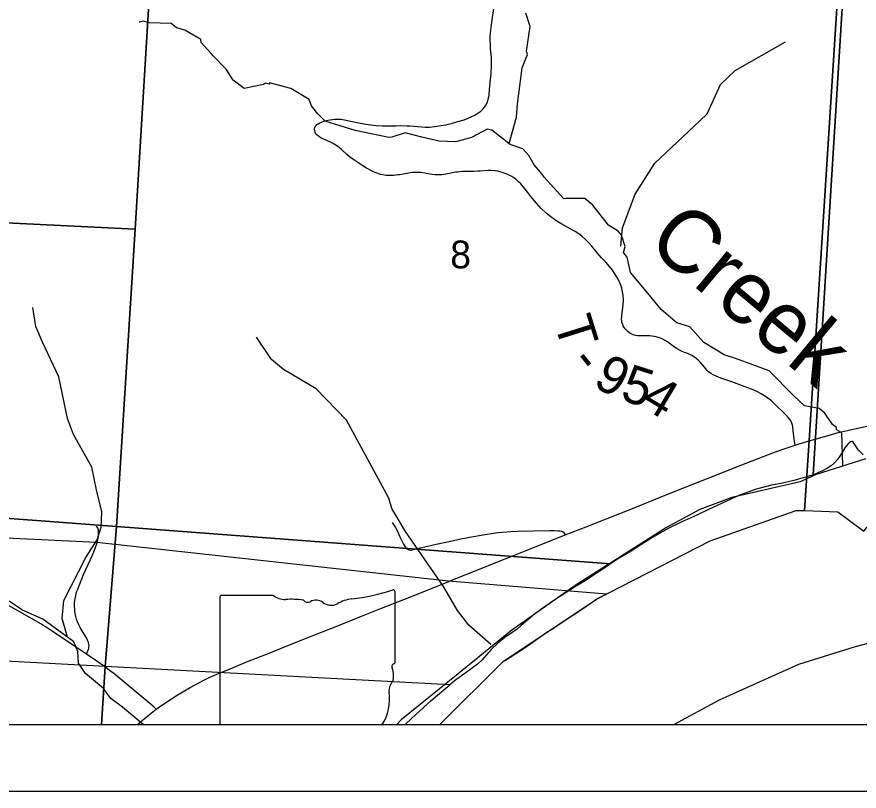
# Model space of a CAD drawing. Extents: x -2.1 to 31.9, y 6.3 to 28.3.
# Drawn here: x 3.117 to 4.384, y 20.344 to 21.508 of the extents above; entities that cross this region are included whole.
import ezdxf

# ---------------------------------------------------------------- set-up
doc = ezdxf.new("R2010")
doc.units = 0
for name, color, linetype in [('Default', 7, 'Continuous'), ('GM_X_Major_River', 7, 'Continuous'), ('GM_X_Minor_River', 7, 'Continuous'), ('GM_X_Minor_River_Text', 7, 'Continuous'), ('GM_X_Section', 7, 'Continuous'), ('GM_X_Section_Text', 7, 'Continuous'), ('GM_X_State_Location', 7, 'Continuous'), ('GM_X_State_Route', 7, 'Continuous'), ('GM_X_Township_Road', 7, 'Continuous'), ('GM_X_Township_Road_Text', 7, 'Continuous'), ('SH_Cut_Line', 7, 'Continuous'), ('SH_Data', 7, 'Continuous')]:
    doc.layers.add(name, color=color, linetype=linetype)

msp = doc.modelspace()

# ---------------------------------------------------------------- linework, layer by layer
at = {"layer": 'Default'}
msp.add_line((3.5023, 20.6384), (3.425, 20.6384), dxfattribs=at)
for points in [[(0.0344, 26.1105), (0.0344, 20.444), (3.7533, 20.444), (3.8489, 20.5389), (3.9894, 20.6326), (4.16, 20.7203), (4.2895, 20.7662), (4.3023, 20.7658), (4.3091, 20.8714), (4.3751, 21.8979), (4.4168, 22.5238), (4.4383, 22.8067), (4.4651, 23.2405), (4.4901, 23.6442), (4.5473, 24.5954), (4.5667, 24.9084), (4.6032, 25.4816), (4.6286, 25.8765), (3.8625, 25.9158), (3.0763, 25.9555), (2.8034, 25.9683), (2.0757, 26.0047), (0.4641, 26.0883)], [(2.565, 20.444), (3.7533, 20.444), (3.8489, 20.5389), (3.8524, 20.5411), (3.8819, 20.56), (3.9131, 20.5819), (3.9243, 20.5893), (3.9388, 20.5991), (3.9535, 20.6088), (3.9664, 20.6173), (3.9829, 20.6284), (3.9898, 20.633), (3.9977, 20.637), (4.0042, 20.6402), (3.7666, 20.6598), (3.2373, 20.718), (2.9743, 20.7306), (2.8967, 20.6256), (2.8379, 20.7139), (2.7774, 20.717)], [(2.8922, 20.444), (3.2442, 20.444), (3.25, 20.5316), (2.4442, 20.5745), (2.2124, 20.5868), (2.2056, 20.479)], [(3.2442, 20.444), (3.7013, 20.444), (3.711, 20.4531), (3.7405, 20.4805), (3.7595, 20.4964), (3.7685, 20.504), (3.25, 20.5316)]]:
    msp.add_lwpolyline(points, close=True, dxfattribs=at)
for points in [[(4.4901, 23.6442), (4.4651, 23.2405), (4.4383, 22.8067), (4.4168, 22.5238), (4.3751, 21.8979), (4.3091, 20.8714), (4.3023, 20.7658), (4.3525, 20.764), (4.3916, 20.7347), (4.4406, 20.7955), (4.5025, 20.8232), (4.6795, 20.8531), (4.9328, 20.8577), (5.1211, 20.8684), (5.1462, 20.8673), (5.351, 20.8306)], [(3.6862, 20.5387), (3.6861, 20.5387), (3.6862, 20.5387), (3.6862, 20.6436)], [(3.4225, 20.635), (3.4225, 20.444), (3.6669, 20.444)]]:
    msp.add_lwpolyline(points, dxfattribs=at)
for centre, radius, start, end in [((3.4255, 20.6354), 0.00305, 98.978, 188.5967), ((3.5207, 20.6617), 0.0296, 231.6404, 271.1117), ((3.5922, 20.9113), 0.2796, 275.8445, 288.9065), ((3.6832, 20.6438), 0.00294, 355.0978, 97.738), ((3.5305, 20.5261), 0.1064, 80.4867, 94.9883), ((3.5547, 20.6365), 0.00855, 219.7921, 297.1024), ((3.5672, 20.6133), 0.0178, 54.4667, 119.1411), ((3.5902, 20.645), 0.0214, 233.8562, 294.8282), ((3.6279, 20.5773), 0.0563, 97.3462, 120.7689), ((3.6855, 20.531), 0.00454, 107.944, 210.337), ((3.683, 20.5383), 0.00314, 289.6038, 7.7341), ((3.6566, 20.5178), 0.0273, 340.033, 23.6496), ((3.6967, 20.4949), 0.0198, 136.8065, 186.9296), ((3.6079, 20.4816), 0.0699, 327.459, 8.9858)]:
    msp.add_arc(centre, radius, start, end, dxfattribs=at)
at = {"layer": 'GM_X_Major_River'}
msp.add_line((4.3946, 20.8439), (4.3197, 20.8204), dxfattribs=at)
for points in [[(4.3197, 20.8204), (4.2959, 20.8093), (4.193, 20.7857), (4.1446, 20.7674), (4.0944, 20.7405), (3.9572, 20.6531), (3.8597, 20.5843), (3.7811, 20.5205), (3.6953, 20.451), (3.6885, 20.444)], [(4.1054, 20.444), (4.1745, 20.4812), (4.1896, 20.4881), (4.2939, 20.5348), (4.379, 20.5615), (4.4841, 20.5889), (4.5359, 20.5965), (4.5718, 20.5943), (4.6974, 20.5759), (4.7587, 20.579), (4.8729, 20.5765), (4.8861, 20.5738), (4.9474, 20.544), (4.9694, 20.5322), (5.0042, 20.519), (5.0757, 20.5039), (5.1135, 20.5021)]]:
    msp.add_lwpolyline(points, dxfattribs=at)
at = {"layer": 'GM_X_Minor_River'}
for points in [[(3.8577, 21.318), (3.8686, 21.3573), (3.8704, 21.377), (3.8772, 21.4318), (3.8855, 21.4516), (3.884, 21.4569), (3.8896, 21.4941), (3.8828, 21.5139)], [(3.8249, 21.3393), (3.8009, 21.3271), (3.7775, 21.3202), (3.7526, 21.3213), (3.7261, 21.3277), (3.7011, 21.3341), (3.6811, 21.3276), (3.6769, 21.3268), (3.6259, 21.3377), (3.5809, 21.3517), (3.5696, 21.3627), (3.5601, 21.3748), (3.5567, 21.3843), (3.5291, 21.4006), (3.4973, 21.4092), (3.4969, 21.407), (3.4913, 21.4088), (3.4882, 21.4069), (3.4588, 21.4004), (3.4425, 21.4133), (3.4319, 21.4296), (3.413, 21.4493), (3.4092, 21.4531), (3.3944, 21.4698), (3.3937, 21.4744), (3.3698, 21.4884), (3.357, 21.4918), (3.349, 21.4982), (3.3162, 21.4993), (3.3075, 21.5019), (3.3014, 21.5004), (3.301, 21.5004)], [(4.026, 21.1635), (4.0282, 21.1912), (4.0475, 21.2418), (4.0769, 21.2882), (4.1447, 21.3518), (4.1557, 21.3628), (4.1757, 21.4069), (4.198, 21.4279), (4.2737, 21.471)], [(3.8874, 21.3001), (3.8781, 21.3098), (3.8595, 21.3166), (3.8315, 21.3382), (3.8248, 21.3394)], [(4.3601, 20.8335), (4.3585, 20.8826), (4.3506, 20.8871), (4.3506, 20.8909), (4.3445, 20.8951), (4.3328, 20.9125), (4.3245, 20.9194), (4.3022, 20.9235), (4.2863, 20.9387), (4.2488, 20.9762), (4.2, 20.9943), (4.1815, 21), (4.1505, 21.0189), (4.1297, 21.042), (4.11, 21.0481), (4.1074, 21.0504), (4.0866, 21.0682), (4.0665, 21.0928), (4.0404, 21.1239), (4.0351, 21.1471), (4.0298, 21.1539), (4.0321, 21.1631), (4.0267, 21.1801), (4.0218, 21.1862), (4.0071, 21.1953), (3.9836, 21.2253), (3.9715, 21.2351), (3.9432, 21.2354), (3.9401, 21.2347), (3.9106, 21.2673), (3.9076, 21.2718), (3.8955, 21.2859), (3.8874, 21.3001)], [(3.1932, 20.5754), (3.1849, 20.6034), (3.1876, 20.6307), (3.2206, 20.6953), (3.2377, 20.7217), (3.2439, 20.7409), (3.2446, 20.764), (3.2365, 20.7969), (3.2296, 20.8313), (3.202, 20.8804), (3.1929, 20.9043), (3.1801, 20.967), (3.1556, 21.0194), (3.1453, 21.0429), (3.1409, 21.0715)], [(3.8302, 20.5646), (3.7973, 20.5934), (3.7802, 20.6156), (3.759, 20.6516), (3.7018, 20.7346), (3.6813, 20.7691), (3.6769, 20.7848), (3.6128, 20.9019), (3.5674, 20.9489), (3.5183, 20.9782), (3.4999, 20.9932), (3.4775, 21.0269)], [(3.307, 20.444), (3.2758, 20.4703), (3.2584, 20.4834), (3.2475, 20.4982), (3.2202, 20.521), (3.2097, 20.5362), (3.2088, 20.5541), (3.2024, 20.5687), (3.195, 20.5739), (3.1558, 20.6028), (3.1252, 20.6163), (3.1026, 20.6311)]]:
    msp.add_lwpolyline(points, dxfattribs=at)
at = {"layer": 'GM_X_Section'}
for points in [[(4.3744, 21.7716), (4.3154, 20.8197), (4.3074, 20.817), (4.2862, 20.8109), (4.2673, 20.8067), (4.2525, 20.804), (4.2279, 20.7975), (4.2033, 20.7884), (4.1836, 20.7796), (4.1586, 20.7678), (4.1401, 20.759), (4.1177, 20.7491), (4.0958, 20.7385), (4.0829, 20.7309), (4.0708, 20.7237), (4.056, 20.7145), (4.0413, 20.705), (4.0209, 20.6929), (4.0125, 20.6875), (4.0103, 20.6856), (3.2668, 20.742), (3.295, 21.1893), (3.3214, 21.6276)], [(4.3903, 20.8498), (4.3835, 20.8569), (4.3767, 20.8675), (4.3751, 20.8698), (4.3736, 20.8698), (4.3713, 20.8694), (4.3672, 20.8656), (4.363, 20.8603), (4.3562, 20.8493), (4.3517, 20.8425), (4.3475, 20.8375), (4.3422, 20.8334), (4.3358, 20.8292), (4.3282, 20.8254), (4.3233, 20.8231), (4.3218, 20.8223), (4.3154, 20.8197), (4.3744, 21.7716)]]:
    msp.add_lwpolyline(points, dxfattribs=at)
for points in [[(2.2801, 21.6751), (3.3214, 21.6276), (3.295, 21.1893), (2.2526, 21.24)], [(3.295, 21.1893), (3.2668, 20.742), (2.4633, 20.8019), (2.2269, 20.8175), (2.2526, 21.24)], [(3.2668, 20.742), (3.25, 20.5316), (2.4442, 20.5745), (2.4633, 20.8019)], [(3.2668, 20.742), (4.0103, 20.6856), (4.0016, 20.6799), (3.9917, 20.6735), (3.9842, 20.6685), (3.9751, 20.6621), (3.9562, 20.6507), (3.9278, 20.6328), (3.9119, 20.6214), (3.896, 20.61), (3.8756, 20.5929), (3.8691, 20.5872), (3.8532, 20.5766), (3.8408, 20.5667), (3.8306, 20.5568), (3.8173, 20.5412), (3.8101, 20.5348), (3.7908, 20.5211), (3.7776, 20.5116), (3.7685, 20.504), (3.25, 20.5316)]]:
    msp.add_lwpolyline(points, close=True, dxfattribs=at)
at = {"layer": 'GM_X_State_Route'}
for points in [[(4.3093, 20.8708), (4.3251, 20.8755), (4.3515, 20.8826), (4.3755, 20.8884), (4.3984, 20.8935), (4.4194, 20.8977), (4.439, 20.9013), (4.459, 20.9044), (4.4797, 20.9072), (4.5005, 20.9097), (4.52, 20.9116), (4.5386, 20.9132), (4.5594, 20.9146), (4.5794, 20.9156), (4.6076, 20.9163), (4.6581, 20.9172), (4.7018, 20.9178), (4.7372, 20.9183), (4.7769, 20.9189), (4.8129, 20.9194)], [(4.2881, 20.8641), (4.2912, 20.8651), (4.307, 20.8702), (4.3093, 20.8708)], [(3.7668, 20.6593), (3.7727, 20.6616), (3.8107, 20.6769), (3.8402, 20.6886), (3.8609, 20.6969), (3.8834, 20.7058), (3.9418, 20.7292), (3.9737, 20.7414), (4.0053, 20.754), (4.046, 20.7702), (4.1003, 20.7919), (4.1573, 20.8145), (4.2055, 20.8337), (4.2414, 20.8479), (4.2585, 20.854), (4.2747, 20.8596), (4.2881, 20.8641)], [(3.3267, 20.4671), (3.3335, 20.4721), (3.3495, 20.4829), (3.3594, 20.4892), (3.3776, 20.4999), (3.3984, 20.5109), (3.4062, 20.5147), (3.4215, 20.5214), (3.4342, 20.5266), (3.4641, 20.5388), (3.4964, 20.5516), (3.5247, 20.5628), (3.5611, 20.5774), (3.6032, 20.5942), (3.6407, 20.6093), (3.6656, 20.6189), (3.699, 20.6324), (3.7482, 20.6518), (3.7668, 20.6593)], [(3.3267, 20.4671), (3.3233, 20.4703), (3.3202, 20.4732), (3.2931, 20.496), (3.2627, 20.5207), (3.2556, 20.5261), (3.2488, 20.5312), (3.2357, 20.5402), (3.2215, 20.55), (3.2037, 20.562), (3.1702, 20.5843), (3.1593, 20.5914), (3.156, 20.5936), (3.1529, 20.5955), (3.1009, 20.6249)], [(3.2983, 20.444), (3.309, 20.4532), (3.3267, 20.4671)]]:
    msp.add_lwpolyline(points, dxfattribs=at)
at = {"layer": 'GM_X_Township_Road'}
for points in [[(4.2881, 20.8641), (4.2874, 20.8696), (4.2864, 20.8781), (4.2854, 20.8857), (4.2845, 20.8925), (4.2838, 20.8956), (4.2824, 20.8991), (4.2805, 20.9024), (4.2778, 20.9059), (4.2736, 20.9105), (4.257, 20.9265), (4.2524, 20.9307), (4.2471, 20.935), (4.242, 20.9386), (4.2371, 20.9415), (4.2305, 20.9449), (4.2225, 20.9484), (4.2115, 20.9527), (4.201, 20.9566), (4.1928, 20.9594), (4.1764, 20.9652), (4.1695, 20.9679), (4.165, 20.97), (4.1613, 20.9722), (4.1579, 20.9748), (4.1552, 20.9772), (4.1515, 20.9814), (4.146, 20.9881), (4.1422, 20.9922), (4.1389, 20.9952), (4.1354, 20.9978), (4.1326, 20.9993), (4.1286, 21.0011), (4.1251, 21.0024), (4.1216, 21.0035), (4.1171, 21.0055), (4.1149, 21.0066), (4.1106, 21.009), (4.1091, 21.01), (4.1065, 21.0117), (4.1006, 21.0162), (4.0961, 21.0196), (4.0924, 21.0219), (4.0879, 21.0241), (4.0838, 21.0257), (4.079, 21.0271), (4.0759, 21.0279), (4.0726, 21.0283), (4.069, 21.0285), (4.0603, 21.0287), (4.0516, 21.0288), (4.0479, 21.0293), (4.0457, 21.0298), (4.0433, 21.0307), (4.0412, 21.0317), (4.0394, 21.0328), (4.0364, 21.035), (4.0343, 21.037), (4.0323, 21.0392), (4.0308, 21.0412), (4.0294, 21.0438), (4.0284, 21.0466), (4.0275, 21.0494), (4.0271, 21.0516), (4.0269, 21.0539), (4.0271, 21.0581), (4.0276, 21.0636), (4.0287, 21.0709), (4.0295, 21.0765), (4.0298, 21.0809), (4.0296, 21.084), (4.0292, 21.0888), (4.0288, 21.0925), (4.0284, 21.0949), (4.0271, 21.1004), (4.0253, 21.1058), (4.0231, 21.111), (4.0203, 21.1165), (4.017, 21.1219), (4.0131, 21.1275), (4.0088, 21.1329), (4.0031, 21.1394), (3.9967, 21.1462), (3.9905, 21.1531), (3.9824, 21.1633), (3.9779, 21.1685), (3.973, 21.1733), (3.967, 21.1785), (3.9625, 21.1819), (3.9571, 21.1855), (3.9508, 21.1893), (3.9371, 21.1966), (3.9312, 21.2), (3.926, 21.2034), (3.9207, 21.2075), (3.9133, 21.2134), (3.9058, 21.2203), (3.8987, 21.2284), (3.8959, 21.2317), (3.8904, 21.2383), (3.8858, 21.2442), (3.8797, 21.252), (3.8752, 21.2573), (3.872, 21.2602), (3.8688, 21.2631), (3.8646, 21.2661), (3.8616, 21.2681), (3.8558, 21.2711), (3.8504, 21.2734), (3.8473, 21.2745), (3.8439, 21.2754), (3.8405, 21.2762), (3.8367, 21.2767), (3.8307, 21.2772), (3.8255, 21.2772), (3.8141, 21.2764), (3.8104, 21.2762), (3.8042, 21.2759), (3.7962, 21.2758), (3.791, 21.2759), (3.7871, 21.2757), (3.7833, 21.2754), (3.7802, 21.275), (3.7776, 21.2746), (3.7623, 21.2716), (3.7562, 21.2708), (3.7513, 21.2706), (3.7464, 21.2707), (3.7421, 21.2711), (3.7355, 21.2725), (3.7306, 21.2734), (3.725, 21.2741), (3.7223, 21.2744), (3.7194, 21.2744), (3.7163, 21.2743), (3.7125, 21.2741), (3.7063, 21.2733), (3.6984, 21.2719), (3.6929, 21.271), (3.6904, 21.2706), (3.6843, 21.2699), (3.6806, 21.2697), (3.6751, 21.2698), (3.6728, 21.2699), (3.6696, 21.2704), (3.6641, 21.2715), (3.6588, 21.2731), (3.6537, 21.2751), (3.6504, 21.2767), (3.6429, 21.281), (3.6377, 21.2844), (3.6253, 21.2926), (3.6177, 21.298), (3.6134, 21.3015), (3.6052, 21.3091), (3.6018, 21.3119), (3.5967, 21.3156), (3.5946, 21.3169), (3.5898, 21.3195), (3.5866, 21.321), (3.5833, 21.3224), (3.5801, 21.3239), (3.5763, 21.3256), (3.5743, 21.3266), (3.5726, 21.3277), (3.5707, 21.3289), (3.5687, 21.3304), (3.5675, 21.332), (3.5665, 21.3334), (3.5658, 21.3351), (3.5653, 21.3369), (3.565, 21.3384), (3.565, 21.3402), (3.5655, 21.3422), (3.566, 21.3434), (3.5672, 21.3449), (3.5684, 21.3463), (3.5702, 21.3476), (3.573, 21.3492), (3.5765, 21.3507), (3.5789, 21.3515), (3.581, 21.3521), (3.5848, 21.353), (3.5882, 21.3534), (3.5921, 21.3539), (3.5954, 21.3543), (3.6009, 21.3546), (3.6051, 21.3544), (3.61, 21.3537), (3.6214, 21.3511), (3.6317, 21.3489), (3.6397, 21.3474), (3.6458, 21.3464), (3.6495, 21.346), (3.6576, 21.3452), (3.6669, 21.3446), (3.6774, 21.3444), (3.6874, 21.3446), (3.6948, 21.3448), (3.7041, 21.3447), (3.7085, 21.3445), (3.7258, 21.343), (3.7314, 21.3427), (3.7378, 21.3426), (3.7452, 21.3433), (3.7525, 21.3444), (3.7617, 21.3461), (3.7708, 21.3482), (3.7804, 21.3508), (3.79, 21.3536), (3.7962, 21.3559), (3.8016, 21.3584), (3.8059, 21.3606), (3.8091, 21.3624), (3.8122, 21.3645), (3.815, 21.3667), (3.8183, 21.3697), (3.8206, 21.3726), (3.8228, 21.3758), (3.8245, 21.3791), (3.8259, 21.3826), (3.8269, 21.3863), (3.8276, 21.3906), (3.8284, 21.3993), (3.8294, 21.4098), (3.8305, 21.4226), (3.8312, 21.4345), (3.8312, 21.4415), (3.831, 21.4481), (3.8299, 21.4598), (3.8295, 21.4671), (3.8293, 21.4733), (3.8294, 21.4789), (3.8301, 21.4884), (3.8312, 21.4963), (3.8322, 21.5038), (3.8348, 21.5212)], [(3.2375, 20.7174), (3.238, 20.7194), (3.2385, 20.7212), (3.2389, 20.7232), (3.2392, 20.725), (3.2395, 20.7273), (3.2397, 20.7295), (3.2398, 20.7314), (3.2399, 20.7332), (3.2398, 20.735), (3.2395, 20.7365), (3.2392, 20.738), (3.2387, 20.7392), (3.2381, 20.7403), (3.2368, 20.7425)], [(3.6817, 20.748), (3.6868, 20.7402), (3.6892, 20.7359), (3.6934, 20.7262), (3.6965, 20.7195), (3.6989, 20.7152), (3.7001, 20.7131), (3.7011, 20.7115), (3.7026, 20.7096), (3.704, 20.7083), (3.7056, 20.7074), (3.7073, 20.7068), (3.7091, 20.7066), (3.7116, 20.7068), (3.7218, 20.7093), (3.7308, 20.7115), (3.7349, 20.7125), (3.7394, 20.7134), (3.7479, 20.7152), (3.7674, 20.7194), (3.7872, 20.7237), (3.7909, 20.7244)], [(3.7909, 20.7244), (3.7982, 20.7258), (3.8184, 20.7293), (3.8374, 20.7323), (3.8417, 20.7329), (3.8479, 20.7336), (3.8603, 20.7346), (3.8708, 20.7349), (3.8938, 20.7353), (3.918, 20.7357), (3.9261, 20.7358), (3.9311, 20.7355), (3.9341, 20.7353), (3.9365, 20.7349), (3.9382, 20.7343), (3.9394, 20.7334), (3.9404, 20.7319), (3.9418, 20.7292)], [(3.2215, 20.55), (3.2239, 20.5552), (3.2246, 20.5572), (3.2251, 20.559), (3.2254, 20.5608), (3.2255, 20.5628), (3.2253, 20.5649), (3.2248, 20.5669), (3.2242, 20.5688), (3.2233, 20.5711), (3.2221, 20.5737), (3.2123, 20.5903), (3.2102, 20.5943), (3.2083, 20.5985), (3.2068, 20.6025), (3.2056, 20.6067), (3.2047, 20.611), (3.2042, 20.6148), (3.2039, 20.618), (3.2036, 20.6216), (3.2036, 20.6246), (3.2037, 20.6274), (3.204, 20.6307), (3.2047, 20.6344), (3.2054, 20.6376), (3.2063, 20.6412), (3.2073, 20.6445), (3.2084, 20.6477), (3.2173, 20.6696), (3.2276, 20.6921), (3.23, 20.6976), (3.2325, 20.7037), (3.2346, 20.7094), (3.2375, 20.7174)]]:
    msp.add_lwpolyline(points, dxfattribs=at)
at = {"layer": 'SH_Cut_Line'}
msp.add_lwpolyline([(0.0344, 20.444), (3.7533, 20.444), (3.8489, 20.5389), (3.9894, 20.6326), (4.16, 20.7203), (4.2895, 20.7662), (4.3023, 20.7658), (4.3525, 20.764), (4.3916, 20.7347), (4.4406, 20.7955), (4.5025, 20.8232), (4.6795, 20.8531), (4.9328, 20.8577), (5.1211, 20.8684), (5.1462, 20.8673), (5.351, 20.8306)], dxfattribs=at)
at = {"layer": 'SH_Data'}
for p, q in [((0.0344, 20.444), (6.8344, 20.444)), ((-0.0656, 20.344), (6.9344, 20.344))]:
    msp.add_line(p, q, dxfattribs=at)

# ---------------------------------------------------------------- texts
at = {"layer": 'GM_X_Minor_River_Text'}
msp.add_text('Creek', height=0.09469, rotation=320.1349, dxfattribs=at).set_placement((4.0619, 21.1646))
at = {"layer": 'GM_X_Section_Text'}
msp.add_text('8', height=0.0419, rotation=0, dxfattribs=at).set_placement((3.7691, 21.1301))
at = {"layer": 'GM_X_State_Location'}
for s in ['s', 'r']:
    msp.add_text(s, height=0.000189, dxfattribs=at).set_placement((3.5514, 20.5216))
msp.add_text('7', height=0.000189, rotation=0, dxfattribs=at).set_placement((3.5228, 20.5078))
at = {"layer": 'GM_X_Township_Road_Text'}
for s, rotation, p in [('T', 287.3731, (3.9249, 21.049)), ('-', 308.0893, (3.9479, 20.9887)), ('9', 331.8752, (3.9819, 20.9539)), ('5', 342.2489, (4.0231, 20.9331)), ('4', 329.0438, (4.0532, 20.9238))]:
    msp.add_text(s, height=0.0568, rotation=rotation, dxfattribs=at).set_placement(p)

doc.saveas('drawing.dxf')
